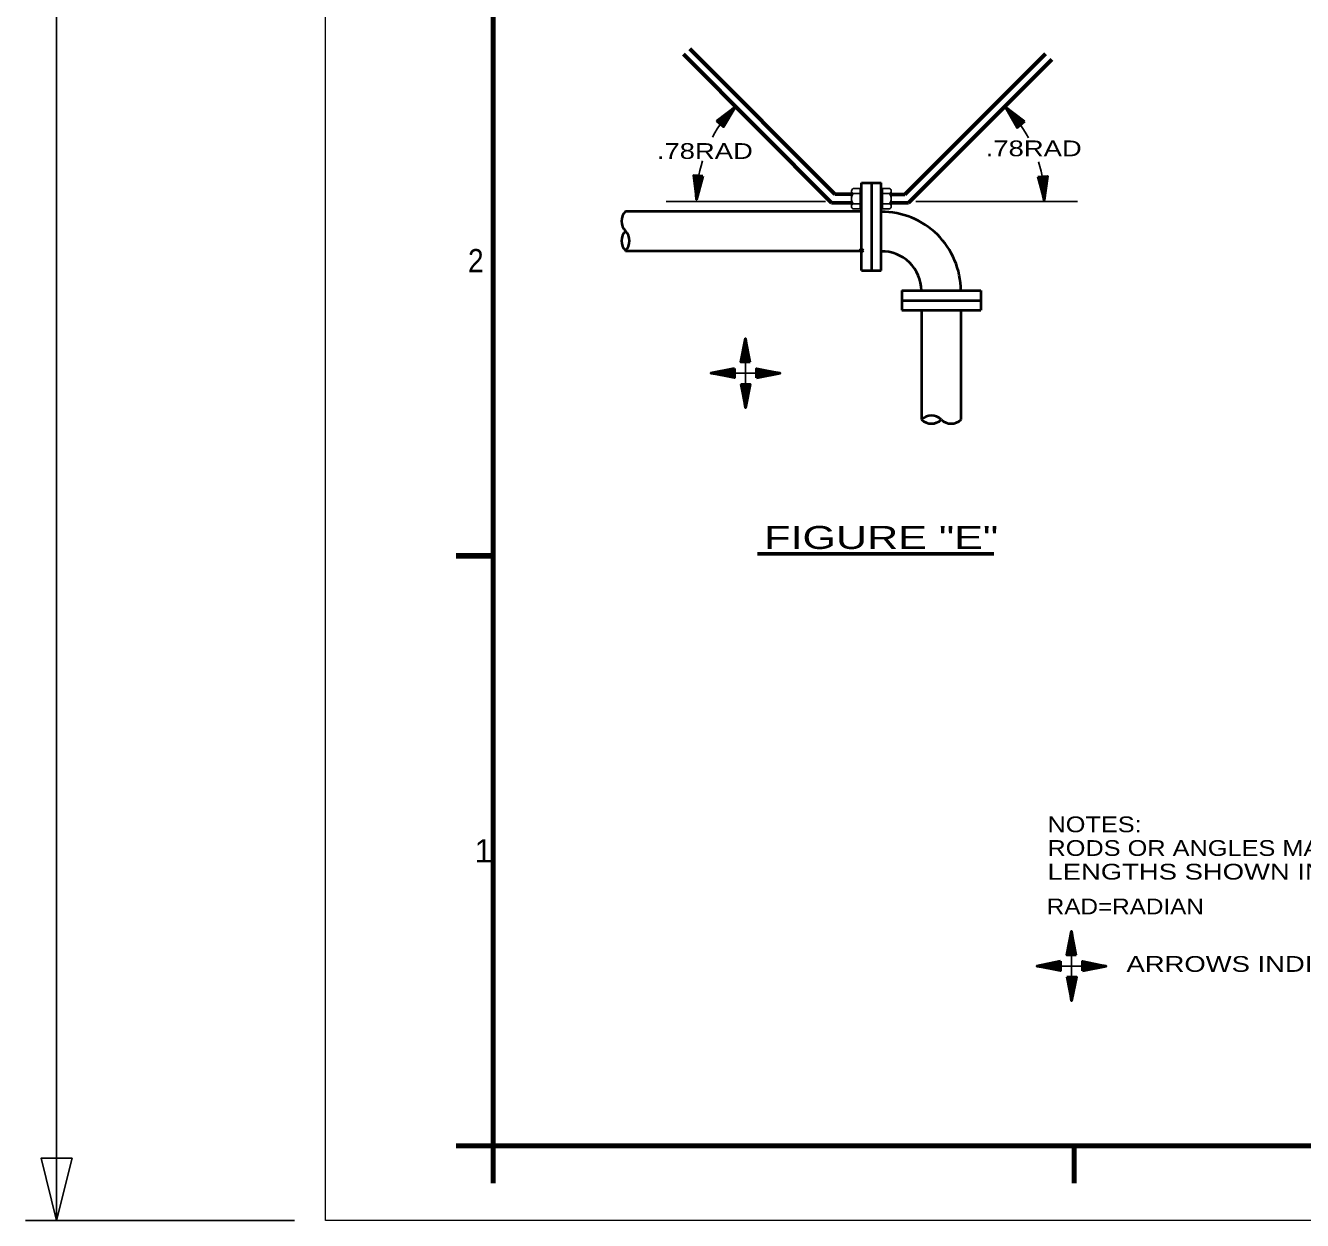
# Model space of a CAD drawing. Extents: x 55 to 190, y 198 to 264.
# Drawn here: x 57.66 to 78.22, y 198.45 to 217.69 of the extents above; entities that cross this region are included whole.
import ezdxf
from ezdxf.enums import TextEntityAlignment as Align

# ---------------------------------------------------------------- set-up
doc = ezdxf.new("R2010")
doc.units = 0
doc.header["$LTSCALE"] = 0.1
doc.header["$PDMODE"] = 32
doc.header["$PDSIZE"] = 0.05
for name, color, linetype, lineweight in [('1', 7, 'Continuous', 25), ('2', 7, 'Continuous', 40), ('3', 7, 'Continuous', 25)]:
    doc.layers.add(name, color=color, linetype=linetype, lineweight=lineweight)

msp = doc.modelspace()

# ---------------------------------------------------------------- linework, layer by layer
at = {"layer": '1', "lineweight": 90}
msp.add_line((65.1915, 209.1512), (64.5915, 209.1512), dxfattribs=at)
at = {"layer": '1', "lineweight": 80}
for p, q in [((65.1915, 199.6512), (64.5915, 199.6512)), ((65.1915, 199.6512), (65.1915, 199.0512)), ((74.5415, 199.6512), (74.5415, 199.0512))]:
    msp.add_line(p, q, dxfattribs=at)
at = {"layer": '1', "lineweight": 13}
msp.add_lwpolyline([(62.4915, 257.8525), (146.5927, 257.8525), (146.5927, 198.4512), (62.4915, 198.4512)], close=True, dxfattribs=at)
at = {"layer": '1', "lineweight": 80}
msp.add_lwpolyline([(65.1915, 256.6525), (145.3927, 256.6525), (145.3927, 199.6512), (65.1915, 199.6512)], close=True, dxfattribs=at)
at = {"layer": '2', "lineweight": 60}
for p, q in [((68.3568, 217.3107), (70.688, 214.9702)), ((68.2517, 217.226), (70.6362, 214.8321)), ((71.8194, 214.9659), (74.0813, 217.2279)), ((71.8755, 214.8318), (74.1829, 217.139)), ((70.9574, 214.9702), (70.688, 214.9702)), ((71.5974, 214.9659), (71.8194, 214.9659)), ((70.9574, 214.8321), (70.6362, 214.8321)), ((71.5974, 214.8318), (71.8755, 214.8318)), ((69.4432, 209.1829), (73.2513, 209.1829))]:
    msp.add_line(p, q, dxfattribs=at)
at = {"layer": '2'}
for p, q in [((69.0936, 216.3905), (68.7986, 216.1404)), ((69.0936, 216.3905), (68.8145, 216.1259)), ((69.0936, 216.3905), (68.8275, 216.1153)), ((68.8407, 216.1034), (69.0936, 216.3905)), ((69.0936, 216.3905), (68.8555, 216.0907)), ((69.0936, 216.3905), (68.8833, 216.0663)), ((73.686, 216.0891), (73.4331, 216.3762)), ((73.4331, 216.3762), (73.7122, 216.1116)), ((73.4331, 216.3762), (73.6434, 216.0521)), ((73.4331, 216.3762), (73.6712, 216.0764)), ((73.4331, 216.3762), (73.6992, 216.101)), ((73.4331, 216.3762), (73.7281, 216.1261)), ((68.4642, 214.8874), (68.4351, 215.2726)), ((68.4642, 214.8874), (68.4724, 215.2702)), ((68.4915, 215.2689), (68.4642, 214.8874)), ((68.4642, 214.8874), (68.5094, 215.2676)), ((68.4642, 214.8874), (68.5264, 215.2668)), ((68.4642, 214.8874), (68.5475, 215.2649)), ((74.0625, 214.8731), (73.9792, 215.2506)), ((74.0625, 214.8731), (74.0003, 215.2525)), ((74.0625, 214.8731), (74.0173, 215.2533)), ((74.0353, 215.2546), (74.0625, 214.8731)), ((74.0625, 214.8731), (74.0543, 215.2559)), ((74.0625, 214.8731), (74.0916, 215.2583)), ((71.1193, 213.7436), (71.1193, 215.1514)), ((71.1193, 215.1514), (71.4363, 215.1514)), ((71.2796, 215.1514), (71.2796, 213.7436)), ((71.4363, 213.7436), (71.4363, 215.1514)), ((67.3188, 214.7003), (71.1193, 214.7003)), ((67.3188, 214.0611), (71.1193, 214.0611)), ((71.1193, 213.7436), (71.4363, 213.7436)), ((71.7712, 213.42), (73.0386, 213.42)), ((71.7712, 213.42), (71.7712, 213.1025)), ((73.0386, 213.42), (73.0386, 213.1025)), ((71.7712, 213.2612), (73.0386, 213.2612)), ((71.7712, 213.1025), (73.0386, 213.1025)), ((72.0861, 213.1025), (72.0861, 211.3419)), ((72.7211, 213.1025), (72.7211, 211.3419)), ((69.2505, 212.6495), (69.1945, 212.2672)), ((69.2505, 212.6495), (69.2318, 212.2672)), ((69.2511, 212.2669), (69.2505, 212.6495)), ((69.2505, 212.6495), (69.286, 212.2667)), ((69.2505, 212.6495), (69.2688, 212.2672)), ((69.2505, 212.6495), (69.3074, 212.2672)), ((68.692, 212.0907), (69.0743, 212.1476)), ((68.692, 212.0907), (69.0749, 212.1262)), ((68.692, 212.0907), (69.0743, 212.109)), ((69.0746, 212.0912), (68.692, 212.0907)), ((68.692, 212.0907), (69.0743, 212.0346)), ((68.692, 212.0907), (69.0743, 212.0719)), ((69.8093, 212.0907), (69.4265, 212.0553)), ((69.4268, 212.0902), (69.8093, 212.0907)), ((69.8093, 212.0907), (69.427, 212.1468)), ((69.8093, 212.0907), (69.427, 212.1095)), ((69.8093, 212.0907), (69.427, 212.0725)), ((69.8093, 212.0907), (69.427, 212.0338)), ((69.2505, 211.5322), (69.1937, 211.9145)), ((69.2505, 211.5322), (69.2151, 211.915)), ((69.2505, 211.5322), (69.2323, 211.9145)), ((69.25, 211.9148), (69.2505, 211.5322)), ((69.2505, 211.5322), (69.3066, 211.9145)), ((69.2505, 211.5322), (69.2693, 211.9145)), ((74.5017, 203.1055), (74.4456, 202.7231)), ((74.5017, 203.1055), (74.4829, 202.7231)), ((74.5023, 202.7229), (74.5017, 203.1055)), ((74.5017, 203.1055), (74.5372, 202.7226)), ((74.5017, 203.1055), (74.52, 202.7231)), ((74.5017, 203.1055), (74.5586, 202.7231)), ((73.9432, 202.5467), (74.3255, 202.6035)), ((73.9432, 202.5467), (74.326, 202.5821)), ((73.9432, 202.5467), (74.3255, 202.5649)), ((74.3258, 202.5472), (73.9432, 202.5467)), ((73.9432, 202.5467), (74.3255, 202.4906)), ((73.9432, 202.5467), (74.3255, 202.5279)), ((75.0605, 202.5467), (74.6777, 202.5112)), ((74.6779, 202.5461), (75.0605, 202.5467)), ((75.0605, 202.5467), (74.6782, 202.6028)), ((75.0605, 202.5467), (74.6782, 202.5655)), ((75.0605, 202.5467), (74.6782, 202.5284)), ((75.0605, 202.5467), (74.6782, 202.4898)), ((74.5017, 201.9881), (74.4448, 202.3705)), ((74.5017, 201.9881), (74.4663, 202.371)), ((74.5017, 201.9881), (74.4835, 202.3705)), ((74.5012, 202.3707), (74.5017, 201.9881)), ((74.5017, 201.9881), (74.5578, 202.3705)), ((74.5017, 201.9881), (74.5205, 202.3705))]:
    msp.add_line(p, q, dxfattribs=at)
at = {"layer": '2', "lineweight": 25}
for p, q in [((71.0976, 215.0615), (70.9846, 215.0615)), ((71.0976, 214.7344), (71.0976, 215.0615)), ((71.458, 214.735), (71.458, 215.0623)), ((71.458, 215.0623), (71.5712, 215.0623)), ((70.5412, 214.8543), (67.975, 214.8543)), ((70.9592, 214.7754), (70.959, 215.0207)), ((71.0976, 214.9802), (70.9838, 214.9802)), ((71.458, 214.9805), (71.572, 214.9805)), ((71.5969, 214.7762), (71.5969, 215.0212)), ((71.9937, 214.8543), (74.5978, 214.8543)), ((71.0976, 214.8154), (70.9838, 214.8154)), ((71.0976, 214.7344), (70.9838, 214.7344)), ((71.458, 214.8162), (71.572, 214.8162)), ((71.458, 214.735), (71.572, 214.735)), ((69.2505, 211.5322), (69.2505, 212.6495)), ((68.692, 212.0907), (69.8093, 212.0907)), ((74.5017, 201.9881), (74.5017, 203.1055)), ((73.9432, 202.5467), (75.0605, 202.5467))]:
    msp.add_line(p, q, dxfattribs=at)
at = {"layer": '2'}
for points in [[(68.7841, 216.1531), (68.8994, 216.0526), (69.0936, 216.3905)], [(68.7841, 216.1531), (69.0936, 216.3905), (68.8693, 216.078)], [(73.7426, 216.1388), (73.6273, 216.0383), (73.4331, 216.3762)], [(73.7426, 216.1388), (73.4331, 216.3762), (73.6574, 216.0637)], [(68.5671, 215.2633), (68.4142, 215.2742), (68.4642, 214.8874)], [(68.5671, 215.2633), (68.4642, 214.8874), (68.4533, 215.2718)], [(73.9596, 215.2491), (74.1125, 215.2599), (74.0625, 214.8731)], [(73.9596, 215.2491), (74.0625, 214.8731), (74.0734, 215.2575)], [(69.3267, 212.2672), (69.1738, 212.2675), (69.2505, 212.6495)], [(69.3267, 212.2672), (69.2505, 212.6495), (69.213, 212.2669)], [(69.0743, 212.1669), (69.0741, 212.014), (68.692, 212.0907)], [(69.0743, 212.1669), (68.692, 212.0907), (69.0746, 212.0531)], [(69.427, 212.0145), (69.4273, 212.1674), (69.8093, 212.0907)], [(69.427, 212.0145), (69.8093, 212.0907), (69.4268, 212.1283)], [(69.1743, 211.9145), (69.2505, 211.5322), (69.2881, 211.9148)], [(69.1743, 211.9145), (69.3273, 211.9142), (69.2505, 211.5322)], [(74.5779, 202.7231), (74.425, 202.7234), (74.5017, 203.1055)], [(74.5779, 202.7231), (74.5017, 203.1055), (74.4641, 202.7229)], [(74.3255, 202.6229), (74.3252, 202.4699), (73.9432, 202.5467)], [(74.3255, 202.6229), (73.9432, 202.5467), (74.3258, 202.5091)], [(74.6782, 202.4705), (75.0605, 202.5467), (74.6779, 202.5842)], [(74.6782, 202.4705), (74.6785, 202.6234), (75.0605, 202.5467)], [(74.4255, 202.3705), (74.5017, 201.9881), (74.5393, 202.3707)], [(74.4255, 202.3705), (74.5785, 202.3702), (74.5017, 201.9881)]]:
    msp.add_lwpolyline(points, dxfattribs=at)
at = {"layer": '2', "lineweight": 25}
for centre, radius, start, end in [((70.5738, 214.8875), 2.1095, 134.56125, 151.61924), ((71.9529, 214.8732), 2.1095, 28.38076, 45.43875), ((70.5738, 214.8875), 2.1095, 162.97004, 180), ((71.9529, 214.8732), 2.1095, 0, 17.02996), ((71.0051, 215.0206), 0.0458, 116.78269, 241.8391), ((71.5507, 215.0211), 0.0458, 298.1609, 63.21731), ((71.1103, 214.8978), 0.1512, 147.00616, 212.94297), ((71.4456, 214.8983), 0.1512, 327.05703, 32.99384), ((71.0048, 214.7751), 0.0458, 117.8877, 242.03419), ((71.5511, 214.7756), 0.0458, 297.96581, 62.1123)]:
    msp.add_arc(centre, radius, start, end, dxfattribs=at)
at = {"layer": '2'}
for centre, radius, start, end in [((67.4832, 214.5377), 0.2286, 135.97881, 224.0225), ((71.4479, 213.4162), 1.27, 0.18395, 90.55137), ((67.4832, 214.22), 0.2286, 135.9775, 224.02119), ((67.1544, 214.22), 0.2286, 315.97881, 44.0225), ((71.4479, 213.4162), 0.635, 0.36759, 91.08432), ((72.2449, 211.1777), 0.2286, 45.9775, 134.02119), ((72.2449, 211.5064), 0.2286, 225.97881, 314.0225), ((72.5626, 211.5064), 0.2286, 225.9775, 314.02119)]:
    msp.add_arc(centre, radius, start, end, dxfattribs=at)
msp.add_point((71.1193, 214.0653), dxfattribs=at)
at = {"layer": '3'}
for p, q in [((58.1602, 257.8525), (58.1602, 198.4512)), ((61.9915, 198.4512), (57.6602, 198.4512))]:
    msp.add_line(p, q, dxfattribs=at)
msp.add_lwpolyline([(58.4102, 199.4512), (58.1602, 198.4512), (57.9102, 199.4512)], close=True, dxfattribs=at)

# ---------------------------------------------------------------- texts
at = {"layer": '1', "width": 0.9}
msp.add_text('2', height=0.375, dxfattribs=at).set_placement((64.9092, 213.7137), align=Align.CENTER)
at = {"layer": '1'}
msp.add_text('1', height=0.375, dxfattribs=at).set_placement((65.0321, 204.2137), align=Align.CENTER)
at = {"layer": '2'}
for s, height, width, p in [('.78RAD', 0.254, 1.3, (68.5968, 215.5386)), ('.78RAD', 0.254, 1.3, (73.8918, 215.5814)), ('FIGURE "E"', 0.3704, 1.4, (71.4368, 209.2599))]:
    msp.add_text(s, height=height, dxfattribs=dict(at, width=width)).set_placement(p, align=Align.CENTER)
for s, width, p in [('NOTES:', 1.2, (74.113, 204.7002)), ('RODS OR ANGLES MAY BE USED FOR SUPPORTS INTERCHANGEABLY. SEE MAXIMUM BRACING', 1.2, (74.113, 204.3192)), ('LENGTHS SHOWN IN TABLE 1 AND MINIMUM SIZES AND SPAN INTERVALS IN TABLE 3.', 1.3, (74.113, 203.9381)), ('RAD=RADIAN', 1.15, (74.1022, 203.3784)), ('ARROWS INDICATE DIRECTION OF AVAILABLE FORCE RESISTANCE, TYPICAL.', 1.3, (75.3854, 202.453))]:
    msp.add_text(s, height=0.254, dxfattribs=dict(at, width=width)).set_placement(p)

doc.saveas('drawing.dxf')
